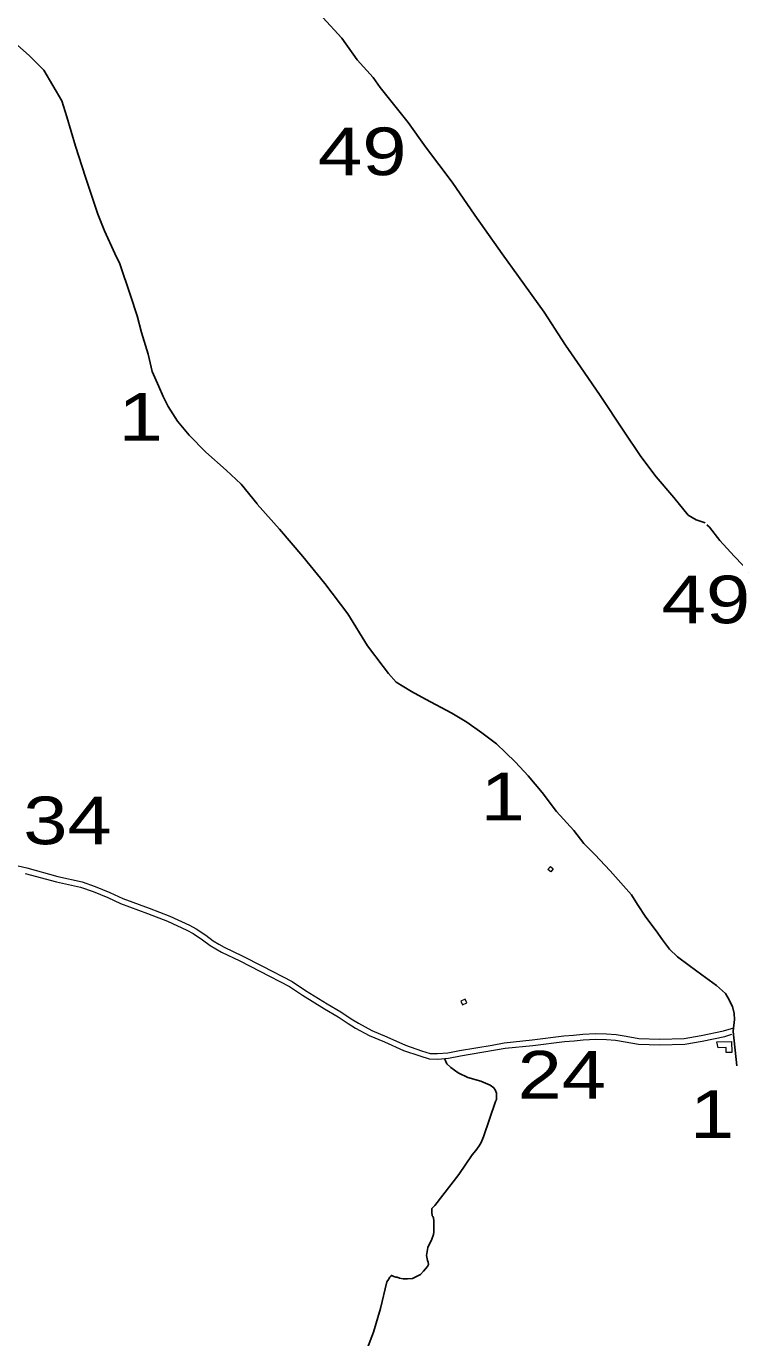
# Model space of a CAD drawing. Extents: x 476989 to 498418, y 4381813 to 4416555.
# Drawn here: x 485670 to 486413, y 4387137 to 4388513 of the extents above; entities that cross this region are included whole.
import ezdxf
from ezdxf.enums import TextEntityAlignment as Align

# ---------------------------------------------------------------- set-up
doc = ezdxf.new("R2010")
doc.units = 0
doc.header["$LTSCALE"] = 20
doc.linetypes.add('MEDIUM_DASHED', pattern=[4.5, 3, -1.5])
for name, color, linetype, lineweight in [('13', 7, 'Continuous', 13), ('36', 7, 'Continuous', 13), ('47', 7, 'Continuous', 13), ('48', 7, 'MEDIUM_DASHED', 13), ('6', 7, 'Continuous', 25)]:
    doc.layers.add(name, color=color, linetype=linetype, lineweight=lineweight)

msp = doc.modelspace()

# ---------------------------------------------------------------- linework, layer by layer
at = {"layer": '36'}
for points in [[(485643.14, 4387636.43), (485670.12, 4387629.89), (485702.71, 4387621.09), (485728.3, 4387615.4), (485741.97, 4387610.63), (485757.5, 4387604.24), (485770.99, 4387598.04), (485798.82, 4387587.68), (485820.32, 4387579.33), (485840.91, 4387569.8), (485847.92, 4387566.17), (485858.19, 4387559.27), (485865.91, 4387553.53), (485871.63, 4387550.07), (485877.42, 4387546.92), (485896.42, 4387537.64), (485917.43, 4387526.69), (485948.87, 4387510.62), (485962.71, 4387501.42), (485985.53, 4387487.21), (485999.97, 4387478.82), (486010.53, 4387471.69), (486018.26, 4387466.93), (486032.24, 4387459.24), (486047.97, 4387452.71), (486067.73, 4387443.96), (486084.52, 4387438.16), (486093.46, 4387435.34), (486101.37, 4387435.15), (486111.95, 4387436.05), (486124.36, 4387438.5), (486158.65, 4387443.94), (486171.22, 4387446.53), (486200.61, 4387449.41), (486233.99, 4387453.74), (486244.06, 4387454.27), (486253.83, 4387455.33), (486267.28, 4387456.04), (486278.77, 4387455.87), (486288.75, 4387455.13), (486299.24, 4387453.26), (486312.7, 4387450.89), (486334.51, 4387450.35), (486360.31, 4387450.88), (486377.98, 4387454), (486401.45, 4387458.91), (486412.26, 4387462.09)], [(485668.67, 4387624.2), (485701.31, 4387615.39), (485726.69, 4387609.74), (485739.89, 4387605.13), (485755.16, 4387598.85), (485768.73, 4387592.61), (485796.73, 4387582.18), (485818.02, 4387573.92), (485838.32, 4387564.52), (485844.92, 4387561.11), (485854.8, 4387554.47), (485862.63, 4387548.64), (485868.7, 4387544.98), (485874.73, 4387541.7), (485893.77, 4387532.39), (485914.74, 4387521.47), (485945.9, 4387505.54), (485959.53, 4387496.48), (485982.5, 4387482.18), (485996.85, 4387473.84), (486007.34, 4387466.75), (486015.3, 4387461.85), (486029.69, 4387453.94), (486045.65, 4387447.31), (486065.57, 4387438.48), (486082.67, 4387432.58), (486092.49, 4387429.48), (486101.55, 4387429.27), (486112.77, 4387430.22), (486125.48, 4387432.73), (486172.11, 4387440.71), (486201.27, 4387443.57), (486234.53, 4387447.88), (486244.53, 4387448.41), (486254.3, 4387449.47), (486267.39, 4387450.16), (486278.51, 4387450), (486288.02, 4387449.29), (486298.22, 4387447.47), (486312.11, 4387445.02), (486334.5, 4387444.47), (486360.89, 4387445.01), (486379.09, 4387448.22), (486402.88, 4387453.21), (486410.26, 4387455.38)]]:
    msp.add_lwpolyline(points, dxfattribs=at)
at = {"layer": '47'}
msp.add_lwpolyline([(486394.5, 4387447.43), (486409.96, 4387447.66), (486410.13, 4387436.18), (486404.24, 4387436.34), (486404.37, 4387441.42), (486395.98, 4387441.26)], close=True, dxfattribs=at)
at = {"layer": '48'}
for points in [[(486222.79, 4387629), (486220.04, 4387625.87), (486217.23, 4387628.33), (486219.98, 4387631.46)], [(486125.88, 4387490.15), (486127.64, 4387486.28), (486132, 4387488.26), (486130.24, 4387492.13)]]:
    msp.add_lwpolyline(points, close=True, dxfattribs=at)
at = {"layer": '6'}
msp.add_line((486033.72, 4388459.48), (486041.26, 4388448.96), dxfattribs=at)
for points in [[(485799.02, 4388756.18), (485799.28, 4388755.64), (485814.2, 4388733.49), (485834.73, 4388709.28), (485864.11, 4388672.95), (485890.94, 4388638.49), (485907.48, 4388616.48), (485933.57, 4388580.5), (485961.99, 4388546.41), (485980.86, 4388522.5), (486000.92, 4388500.56), (486016.79, 4388478.01), (486033.78, 4388459.37)], [(485648.4, 4388503.95), (485672.73, 4388482.48), (485688.17, 4388467.01), (485707.06, 4388435), (485712.35, 4388418.05), (485721.25, 4388387.26), (485731.78, 4388354.89), (485744.85, 4388316.19), (485751.85, 4388298.7), (485762.78, 4388274.7), (485768, 4388263.85), (485779.02, 4388230.66), (485785.91, 4388209.4), (485790.76, 4388192.02), (485797.49, 4388169.1), (485801.96, 4388151.04), (485808.65, 4388135.09), (485813.43, 4388124.82), (485818.42, 4388114.08), (485828.47, 4388098.7), (485840.76, 4388084.25), (485858.12, 4388066.2), (485879.3, 4388047.48), (485895.16, 4388032.58), (485911.89, 4388012.02)], [(486041.26, 4388448.96), (486070.33, 4388412.2), (486088.62, 4388386.55), (486116.6, 4388349.44), (486140.39, 4388314.86), (486164.8, 4388280.35), (486169.29, 4388274.24)], [(486169.13, 4388274.35), (486186.31, 4388250.53), (486213.19, 4388213.09), (486235.61, 4388178.6), (486251.45, 4388155.76), (486271.85, 4388125.77), (486296.82, 4388088.37), (486314.6, 4388061.76), (486330.73, 4388040.49), (486349.4, 4388018.73), (486364.43, 4388000.31), (486372.86, 4387995.35), (486382.16, 4387992.25)], [(485912.17, 4388011.78), (485935.61, 4387985.33), (485960.06, 4387956.84), (485983.16, 4387928.35), (486007.28, 4387896.47), (486027.88, 4387862.88), (486044.27, 4387841.38), (486049.75, 4387833.89), (486058.02, 4387825.05), (486074.09, 4387815.1), (486088.73, 4387807.17), (486116.23, 4387792.4)], [(486383.88, 4387990.09), (486386.63, 4387987.64), (486397.48, 4387973.58), (486412.62, 4387957.15), (486430.7, 4387938.38), (486461.98, 4387901.19), (486486.91, 4387869.73), (486502.64, 4387845.57), (486522.26, 4387819.72), (486543.26, 4387788.72)], [(486116.23, 4387792.4), (486132.03, 4387782.95), (486147.96, 4387771.75), (486163.27, 4387760.17), (486172.57, 4387751.14), (486183, 4387741), (486196.38, 4387726.7), (486211.2, 4387709.12), (486226.06, 4387689.1), (486244.26, 4387669.22), (486254.87, 4387655.62), (486266.52, 4387644.16), (486282.31, 4387626.78), (486304.74, 4387601.82), (486311.03, 4387591.7), (486319.95, 4387578.44), (486330.78, 4387563.95), (486337.26, 4387554.38), (486344.84, 4387544.52), (486353.11, 4387536.82), (486365.48, 4387527.49), (486378.58, 4387517.9), (486394.08, 4387506.62), (486403.68, 4387498.03), (486406.02, 4387494.04)], [(486406.02, 4387494.04), (486410.83, 4387484.53), (486412.59, 4387477.02), (486412.95, 4387470.73), (486411.61, 4387458.73)], [(486411.61, 4387458.24), (486415.3, 4387422.43)], [(486108.72, 4387429.88), (486111.15, 4387424.2), (486115.09, 4387420.58), (486123.07, 4387414.99), (486132.97, 4387410.05), (486146.69, 4387406.04), (486156.54, 4387401.92), (486160.35, 4387399.14), (486162.24, 4387396.44), (486163.03, 4387393.52), (486163.22, 4387390.05), (486163.01, 4387387.04), (486162.1, 4387384.84), (486149.71, 4387347.62), (486147.02, 4387341.86), (486144.83, 4387338.28), (486141.42, 4387333.4), (486137.75, 4387328.8), (486123.51, 4387308.31), (486098.49, 4387275.55)], [(486098.49, 4387275.55), (486095.45, 4387272.46), (486095.42, 4387270.58), (486095.4, 4387269.3), (486095.39, 4387268.63), (486095.81, 4387264.82)], [(486019.79, 4387105.48), (486034.18, 4387142.83), (486041.39, 4387167.75), (486048.03, 4387195.58), (486049.73, 4387197.92), (486050.22, 4387198.85), (486051.3, 4387200.5), (486052.27, 4387201.5), (486053.26, 4387202.33), (486053.18, 4387202.28), (486052.94, 4387202.28), (486054.06, 4387201.94), (486055.28, 4387201.23), (486057.62, 4387200.6), (486058.76, 4387200.43), (486061.5, 4387199.5), (486065.29, 4387198.87), (486069.79, 4387198.81), (486074.96, 4387199.22), (486079.22, 4387201.03), (486083.33, 4387203.26), (486086.51, 4387206.74), (486088.66, 4387209.06), (486090.93, 4387211.75), (486091.67, 4387213.64), (486091.33, 4387216.29), (486090.88, 4387218.02), (486090.18, 4387221.36), (486089.63, 4387223.21), (486091.15, 4387231.55), (486095.34, 4387240.23), (486097, 4387245.29), (486097.29, 4387247.57), (486097.32, 4387249.61), (486097.36, 4387252.18), (486097.33, 4387255.71), (486097.39, 4387259.56), (486097, 4387262.75), (486096.29, 4387264.23), (486095.81, 4387264.86)]]:
    msp.add_lwpolyline(points, dxfattribs=at)

# ---------------------------------------------------------------- texts
at = {"layer": '13', "width": 1.25}
for s, p in [('34', (485712.96, 4387654.82)), ('24', (486231.73, 4387387.95))]:
    msp.add_text(s, height=50, dxfattribs=at).set_placement(p, align=Align.CENTER)
at = {"layer": '6', "width": 1.25}
for s, p in [('49', (486022.33, 4388356.95)), ('1', (485789.69, 4388078.22)), ('49', (486382.99, 4387886.71)), ('1', (486169.71, 4387679.88)), ('1', (486389.45, 4387346.57))]:
    msp.add_text(s, height=50, dxfattribs=at).set_placement(p, align=Align.CENTER)

doc.saveas('drawing.dxf')
